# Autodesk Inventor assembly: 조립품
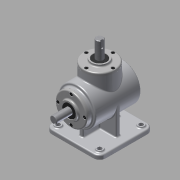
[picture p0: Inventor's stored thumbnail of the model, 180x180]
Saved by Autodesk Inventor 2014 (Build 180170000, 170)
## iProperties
Created: 2015-07
Part Number: 조립품
Document SubType Name: Assembly
Designer: L-10
Author: L-10
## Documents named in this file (14)
- C:\Users\L-10\Desktop\450706V1004\조립품.iam
- C:\Users\L-10\Desktop\450706V1004\본체.ipt
- C:\Users\L-10\Desktop\450706V1004\커버.ipt
- C:\Users\L-10\Desktop\450706V1004\베어링 6203.ipt
- C:\Users\L-10\Desktop\450706V1004\메인 축.ipt
- 메인 축.ipt
- C:\Users\L-10\Desktop\450706V1004\키 5x5.ipt
- C:\Users\L-10\Desktop\450706V1004\메인 베벨기어.ipt
- C:\Users\L-10\Desktop\450706V1004\오일실.ipt
- C:\Users\L-10\Desktop\450706V1004\서브 축.ipt
- 서브 축.ipt
- C:\Users\L-10\Desktop\450706V1004\키 4x4.ipt
- C:\Users\L-10\Desktop\450706V1004\서브 베벨기어.ipt
- C:\Users\L-10\Desktop\450706V1004\M4.ipt
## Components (8 placed, 1 different names)
1. M4:1 — 각도:1
2. M4:2 — 각도:2
3. M4:3 — 각도:3
4. M4:4 — 각도:4
5. M4:5 — 각도:5
6. M4:6 — 각도:6
7. M4:7 — 각도:7
8. M4:8 — 각도:8
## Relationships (8: Angle 8)
- 각도:1 [Angle]: M4:1
- 각도:2 [Angle]: M4:2
- 각도:3 [Angle]: M4:3
- 각도:4 [Angle]: M4:4
- 각도:5 [Angle]: M4:5
- 각도:6 [Angle]: M4:6
- 각도:7 [Angle]: M4:7
- 각도:8 [Angle]: M4:8
